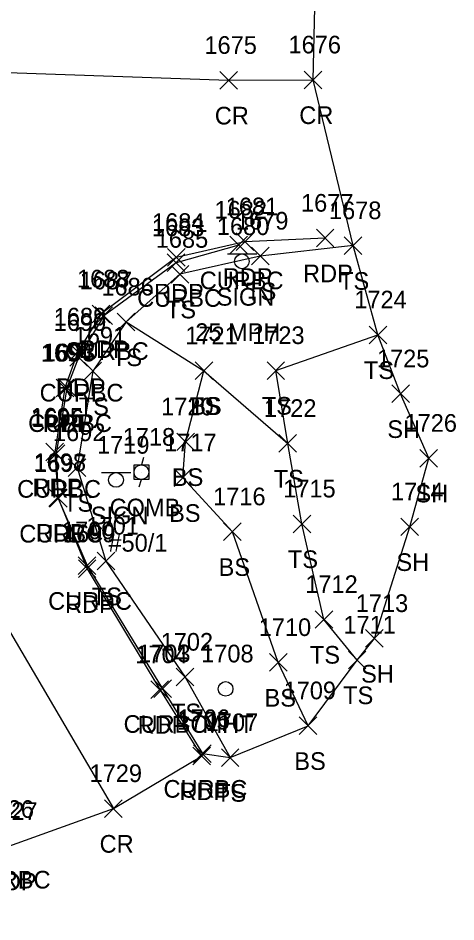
# Model space of a CAD drawing. Extents: x 1716490 to 1717645, y 888034 to 890004.
# Drawn here: x 1717595.6 to 1717645.2, y 888181.8 to 888284.2 of the extents above; entities that cross this region are included whole.
import ezdxf

# ---------------------------------------------------------------- set-up
doc = ezdxf.new("R2010")
doc.units = 0
for name, color, linetype in [('L_A', 7, 'Continuous'), ('L_I', 7, 'Continuous'), ('L_TIC', 7, 'Continuous'), ('LELB', 7, 'Continuous'), ('LSOGP', 7, 'Continuous'), ('P_A', 7, 'Continuous'), ('P_I', 7, 'Continuous'), ('P_TIC', 7, 'Continuous'), ('PET', 7, 'Continuous'), ('PRC', 7, 'Continuous'), ('R_A', 7, 'Continuous'), ('R_I', 7, 'Continuous'), ('R_TIC', 7, 'Continuous'), ('RC', 7, 'Continuous'), ('S_A', 7, 'Continuous'), ('S_C', 7, 'Continuous'), ('S_I', 7, 'Continuous'), ('SSGN', 7, 'Continuous'), ('U_A', 7, 'Continuous'), ('U_C', 7, 'Continuous'), ('U_I', 7, 'Continuous'), ('UP', 7, 'Continuous'), ('UTMH', 7, 'Continuous')]:
    doc.layers.add(name, color=color, linetype=linetype)

msp = doc.modelspace()

# ---------------------------------------------------------------- linework, layer by layer
at = {"layer": 'L_TIC'}
for points in [[(1717632.57, 888257.39), (1717634.57, 888259.39)], [(1717634.57, 888257.39), (1717632.57, 888259.39)], [(1717622.03, 888256.21), (1717624.03, 888258.21)], [(1717624.03, 888256.21), (1717622.03, 888258.21)], [(1717612.92, 888254.15), (1717614.92, 888256.15)], [(1717614.92, 888254.15), (1717612.92, 888256.15)], [(1717606.81, 888248.74), (1717608.81, 888250.74)], [(1717608.81, 888248.74), (1717606.81, 888250.74)], [(1717606.81, 888248.74), (1717608.81, 888250.74)], [(1717608.81, 888248.74), (1717606.81, 888250.74)], [(1717635.39, 888247.28), (1717637.39, 888249.28)], [(1717637.39, 888247.28), (1717635.39, 888249.28)], [(1717603.04, 888243.18), (1717605.04, 888245.18)], [(1717605.04, 888243.18), (1717603.04, 888245.18)], [(1717615.65, 888243.22), (1717617.65, 888245.22)], [(1717617.65, 888243.22), (1717615.65, 888245.22)], [(1717615.65, 888243.22), (1717617.65, 888245.22)], [(1717617.65, 888243.22), (1717615.65, 888245.22)], [(1717623.8, 888243.24), (1717625.8, 888245.24)], [(1717625.8, 888243.24), (1717623.8, 888245.24)], [(1717637.96, 888240.6), (1717639.96, 888242.6)], [(1717639.96, 888240.6), (1717637.96, 888242.6)], [(1717613.57, 888235.16), (1717615.57, 888237.16)], [(1717615.57, 888235.16), (1717613.57, 888237.16)], [(1717625.15, 888234.98), (1717627.15, 888236.98)], [(1717627.15, 888234.98), (1717625.15, 888236.98)], [(1717625.15, 888234.98), (1717627.15, 888236.98)], [(1717627.15, 888234.98), (1717625.15, 888236.98)], [(1717641.15, 888233.3), (1717643.15, 888235.3)], [(1717643.15, 888233.3), (1717641.15, 888235.3)], [(1717601.26, 888232.24), (1717603.26, 888234.24)], [(1717603.26, 888232.24), (1717601.26, 888234.24)], [(1717613.25, 888231.09), (1717615.25, 888233.09)], [(1717615.25, 888231.09), (1717613.25, 888233.09)], [(1717626.76, 888225.86), (1717628.76, 888227.86)], [(1717628.76, 888225.86), (1717626.76, 888227.86)], [(1717639, 888225.53), (1717641, 888227.53)], [(1717641, 888225.53), (1717639, 888227.53)], [(1717618.87, 888224.97), (1717620.87, 888226.97)], [(1717620.87, 888224.97), (1717618.87, 888226.97)], [(1717604.53, 888221.65), (1717606.53, 888223.65)], [(1717606.53, 888221.65), (1717604.53, 888223.65)], [(1717629.26, 888215.03), (1717631.26, 888217.03)], [(1717631.26, 888215.03), (1717629.26, 888217.03)], [(1717634.99, 888212.88), (1717636.99, 888214.88)], [(1717636.99, 888212.88), (1717634.99, 888214.88)], [(1717624.07, 888210.16), (1717626.07, 888212.16)], [(1717626.07, 888210.16), (1717624.07, 888212.16)], [(1717633.03, 888210.44), (1717635.03, 888212.44)], [(1717635.03, 888210.44), (1717633.03, 888212.44)], [(1717613.5, 888208.5), (1717615.5, 888210.5)], [(1717615.5, 888208.5), (1717613.5, 888210.5)], [(1717627.46, 888202.99), (1717629.46, 888204.99)], [(1717629.46, 888202.99), (1717627.46, 888204.99)], [(1717618.62, 888199.38), (1717620.62, 888201.38)], [(1717620.62, 888199.38), (1717618.62, 888201.38)]]:
    msp.add_lwpolyline(points, dxfattribs=at)
at = {"layer": 'LELB'}
for points in [[(1717633.57, 888258.39), (1717623.03, 888257.21), (1717613.92, 888255.15), (1717607.81, 888249.74), (1717604.04, 888244.18), (1717602.26, 888233.24), (1717605.53, 888222.65), (1717614.5, 888209.5), (1717619.62, 888200.38)], [(1717607.81, 888249.74), (1717616.65, 888244.22), (1717626.15, 888235.98)], [(1717634.03, 888211.44), (1717630.26, 888216.03), (1717627.76, 888226.86), (1717626.15, 888235.98), (1717624.8, 888244.24), (1717636.39, 888248.28)], [(1717628.46, 888203.99), (1717625.07, 888211.16), (1717619.87, 888225.97), (1717614.25, 888232.09), (1717614.57, 888236.16), (1717616.65, 888244.22)]]:
    msp.add_lwpolyline(points, dxfattribs=at)
at = {"layer": 'LSOGP'}
msp.add_lwpolyline([(1717512.34, 888207.14), (1717547.36, 888203.24), (1717562.88, 888195.85), (1717574.35, 888181.76), (1717589.34, 888189.72), (1717590.1, 888189.33), (1717594.16, 888190.55), (1717594.52, 888190.33), (1717606.37, 888194.61), (1717616.38, 888200.56), (1717616.48, 888200.84), (1717619.62, 888200.38), (1717628.46, 888203.99), (1717634.03, 888211.44), (1717635.99, 888213.88), (1717640, 888226.53), (1717642.15, 888234.3), (1717638.96, 888241.6), (1717636.39, 888248.28), (1717633.57, 888258.39), (1717629.03, 888277.17), (1717629.47, 888295.32)], dxfattribs=at)
at = {"layer": 'P_TIC'}
for points in [[(1717618.44, 888276.12), (1717620.44, 888278.12)], [(1717620.44, 888276.12), (1717618.44, 888278.12)], [(1717628.03, 888276.17), (1717630.03, 888278.17)], [(1717630.03, 888276.17), (1717628.03, 888278.17)], [(1717629.4, 888258.24), (1717631.4, 888260.24)], [(1717631.4, 888258.24), (1717629.4, 888260.24)], [(1717620.29, 888257.83), (1717622.29, 888259.83)], [(1717622.29, 888257.83), (1717620.29, 888259.83)], [(1717612.5, 888256.06), (1717614.5, 888258.06)], [(1717614.5, 888256.06), (1717612.5, 888258.06)], [(1717603.98, 888249.65), (1717605.98, 888251.65)], [(1717605.98, 888249.65), (1717603.98, 888251.65)], [(1717601.35, 888245.34), (1717603.35, 888247.34)], [(1717603.35, 888245.34), (1717601.35, 888247.34)], [(1717599.88, 888241.26), (1717601.88, 888243.26)], [(1717601.88, 888241.26), (1717599.88, 888243.26)], [(1717598.72, 888234), (1717600.72, 888236)], [(1717600.72, 888234), (1717598.72, 888236)], [(1717599.06, 888228.84), (1717601.06, 888230.84)], [(1717601.06, 888228.84), (1717599.06, 888230.84)], [(1717602.4, 888220.78), (1717604.4, 888222.78)], [(1717604.4, 888220.78), (1717602.4, 888222.78)], [(1717610.63, 888207.08), (1717612.63, 888209.08)], [(1717612.63, 888207.08), (1717610.63, 888209.08)], [(1717615.38, 888199.56), (1717617.38, 888201.56)], [(1717617.38, 888199.56), (1717615.38, 888201.56)], [(1717605.37, 888193.61), (1717607.37, 888195.61)], [(1717607.37, 888193.61), (1717605.37, 888195.61)]]:
    msp.add_lwpolyline(points, dxfattribs=at)
at = {"layer": 'PET'}
msp.add_lwpolyline([(1717630.4, 888259.24), (1717621.29, 888258.83), (1717613.5, 888257.06), (1717604.98, 888250.65), (1717602.35, 888246.34), (1717600.88, 888242.26), (1717599.72, 888235), (1717600.06, 888229.84), (1717603.4, 888221.78), (1717611.63, 888208.08), (1717616.38, 888200.56)], dxfattribs=at)
at = {"layer": 'PRC'}
for points in [[(1717436.1, 888262.99), (1717458.49, 888266.27), (1717492.01, 888269.4), (1717536.7, 888274.82), (1717555.46, 888275.73), (1717587.78, 888278.25), (1717619.44, 888277.12), (1717629.03, 888277.17)], [(1717555.46, 888275.73), (1717576.67, 888244.75), (1717588.48, 888225.03), (1717606.37, 888194.61)]]:
    msp.add_lwpolyline(points, dxfattribs=at)
at = {"layer": 'R_TIC'}
for points in [[(1717619.59, 888257.45), (1717621.59, 888259.45)], [(1717621.59, 888257.45), (1717619.59, 888259.45)], [(1717612.48, 888255.46), (1717614.48, 888257.46)], [(1717614.48, 888255.46), (1717612.48, 888257.46)], [(1717604.29, 888249.44), (1717606.29, 888251.44)], [(1717606.29, 888249.44), (1717604.29, 888251.44)], [(1717601.42, 888244.73), (1717603.42, 888246.73)], [(1717603.42, 888244.73), (1717601.42, 888246.73)], [(1717600.11, 888241.28), (1717602.11, 888243.28)], [(1717602.11, 888241.28), (1717600.11, 888243.28)], [(1717598.88, 888233.83), (1717600.88, 888235.83)], [(1717600.88, 888233.83), (1717598.88, 888235.83)], [(1717599.12, 888228.75), (1717601.12, 888230.75)], [(1717601.12, 888228.75), (1717599.12, 888230.75)], [(1717602.39, 888221.13), (1717604.39, 888223.13)], [(1717604.39, 888221.13), (1717602.39, 888223.13)], [(1717610.95, 888207.19), (1717612.95, 888209.19)], [(1717612.95, 888207.19), (1717610.95, 888209.19)], [(1717615.48, 888199.84), (1717617.48, 888201.84)], [(1717617.48, 888199.84), (1717615.48, 888201.84)]]:
    msp.add_lwpolyline(points, dxfattribs=at)
at = {"layer": 'RC'}
msp.add_lwpolyline([(1717620.59, 888258.45), (1717613.48, 888256.46), (1717605.29, 888250.44), (1717602.42, 888245.73), (1717601.11, 888242.28), (1717599.88, 888234.83), (1717600.12, 888229.75), (1717603.39, 888222.13), (1717611.95, 888208.19), (1717616.48, 888200.84)], dxfattribs=at)
at = {"layer": 'SSGN'}
for p, q in [((1717619.31, 888257.45), (1717622.64, 888257.45)), ((1717620.95, 888256.61), (1717620.95, 888256.61)), ((1717605.03, 888232.67), (1717608.36, 888232.67)), ((1717606.67, 888231.84), (1717606.67, 888231.84))]:
    msp.add_line(p, q, dxfattribs=at)
for centre in [(1717620.95, 888256.61), (1717606.67, 888231.84)]:
    msp.add_circle(centre, 0.833, dxfattribs=at)
at = {"layer": 'UP'}
for p, q in [((1717609.8, 888234.38), (1717609.55, 888233.55)), ((1717608.72, 888231.88), (1717608.72, 888233.55)), ((1717608.72, 888233.55), (1717610.39, 888233.55)), ((1717609.55, 888232.72), (1717609.55, 888232.72)), ((1717610.39, 888233.55), (1717610.39, 888231.88)), ((1717610.39, 888231.88), (1717608.72, 888231.88)), ((1717609.3, 888231.05), (1717609.55, 888231.88))]:
    msp.add_line(p, q, dxfattribs=at)
msp.add_circle((1717609.55, 888232.72), 0.833, dxfattribs=at)
at = {"layer": 'UTMH'}
for p, q in [((1717619.1, 888208.17), (1717619.1, 888208.17)), ((1717619.93, 888208.17), (1717619.93, 888208.17))]:
    msp.add_line(p, q, dxfattribs=at)
msp.add_circle((1717619.1, 888208.17), 0.833, dxfattribs=at)

# ---------------------------------------------------------------- texts
at = {"layer": 'L_A'}
for s, p in [('TS', (1717631.98, 888253.39)), ('TS', (1717621.44, 888252.21)), ('TS', (1717612.33, 888250.15)), ('TS', (1717606.22, 888244.74)), ('TS', (1717606.22, 888244.74)), ('TS', (1717634.8, 888243.28)), ('TS', (1717602.45, 888239.18)), ('TS', (1717615.06, 888239.22)), ('BS', (1717615.09, 888239.22)), ('TS', (1717623.21, 888239.24)), ('SH', (1717637.45, 888236.6)), ('BS', (1717613.01, 888231.16)), ('TS', (1717624.56, 888230.98)), ('TS', (1717624.56, 888230.98)), ('SH', (1717640.64, 888229.3)), ('TS', (1717600.67, 888228.24)), ('BS', (1717612.69, 888227.09)), ('TS', (1717626.17, 888221.86)), ('SH', (1717638.49, 888221.53)), ('BS', (1717618.31, 888220.97)), ('TS', (1717603.93, 888217.65)), ('TS', (1717628.67, 888211.03)), ('SH', (1717634.48, 888208.88)), ('BS', (1717623.52, 888206.16)), ('TS', (1717632.44, 888206.44)), ('TS', (1717612.91, 888204.5)), ('BS', (1717626.9, 888198.99)), ('TS', (1717618.03, 888195.38))]:
    msp.add_text(s, height=2, dxfattribs=at).set_placement(p)
at = {"layer": 'L_I'}
for s, p in [('1678', (1717630.83, 888261.39)), ('1679', (1717620.28, 888260.21)), ('1685', (1717611.18, 888258.15)), ('1686', (1717605.01, 888252.74)), ('1686', (1717605.01, 888252.74)), ('1724', (1717633.7, 888251.28)), ('1691', (1717601.87, 888247.18)), ('1721', (1717614.53, 888247.22)), ('1721', (1717614.53, 888247.22)), ('1723', (1717622.11, 888247.24)), ('1725', (1717636.27, 888244.6)), ('1720', (1717611.79, 888239.16)), ('1722', (1717623.46, 888238.98)), ('1722', (1717623.46, 888238.98)), ('1726', (1717639.4, 888237.3)), ('1692', (1717599.52, 888236.24)), ('1717', (1717612.13, 888235.09)), ('1715', (1717625.64, 888229.86)), ('1716', (1717617.69, 888228.97)), ('1714', (1717637.87, 888229.53)), ('1701', (1717603.32, 888225.65)), ('1712', (1717628.14, 888219.03)), ('1713', (1717633.87, 888216.88)), ('1710', (1717622.86, 888214.16)), ('1711', (1717632.47, 888214.44)), ('1702', (1717611.73, 888212.5)), ('1709', (1717625.68, 888206.99)), ('1707', (1717616.85, 888203.38))]:
    msp.add_text(s, height=2, dxfattribs=at).set_placement(p)
at = {"layer": 'P_A'}
for s, p in [('CR', (1717617.88, 888272.12)), ('CR', (1717627.46, 888272.17)), ('RDP', (1717627.89, 888254.24)), ('RDP', (1717618.78, 888253.83)), ('RDP', (1717610.98, 888252.06)), ('RDP', (1717602.47, 888245.65)), ('RDP', (1717599.84, 888241.34)), ('RDP', (1717598.37, 888237.26)), ('RDP', (1717597.2, 888230)), ('RDP', (1717597.55, 888224.84)), ('RDP', (1717600.88, 888216.78)), ('RDP', (1717609.12, 888203.08)), ('RDP', (1717613.87, 888195.56)), ('CR', (1717604.81, 888189.61)), ('RDP', (1717592.01, 888185.33))]:
    msp.add_text(s, height=2, dxfattribs=at).set_placement(p)
at = {"layer": 'P_I'}
for s, p in [('1675', (1717616.7, 888280.12)), ('1676', (1717626.24, 888280.17)), ('1681', (1717619.12, 888261.83)), ('1677', (1717627.66, 888262.24)), ('1684', (1717610.76, 888260.06)), ('1688', (1717602.24, 888253.65)), ('1689', (1717599.61, 888249.34)), ('1694', (1717598.14, 888245.26)), ('1695', (1717596.98, 888238)), ('1698', (1717597.32, 888232.84)), ('1699', (1717600.65, 888224.78)), ('1704', (1717608.86, 888211.08)), ('1705', (1717613.61, 888203.56)), ('1729', (1717603.67, 888197.61)), ('1427', (1717591.82, 888193.33))]:
    msp.add_text(s, height=2, dxfattribs=at).set_placement(p)
at = {"layer": 'R_A'}
for p in [(1717616.17, 888253.45), (1717609.07, 888251.46), (1717600.87, 888245.44), (1717598.01, 888240.73), (1717596.7, 888237.28), (1717595.46, 888229.83), (1717595.7, 888224.75), (1717598.97, 888217.13), (1717607.53, 888203.19), (1717612.06, 888195.84), (1717589.74, 888185.55)]:
    msp.add_text('CURBC', height=2, dxfattribs=at).set_placement(p)
at = {"layer": 'R_I'}
for s, p in [('1682', (1717617.85, 888261.45)), ('1683', (1717610.74, 888259.46)), ('1687', (1717602.55, 888253.44)), ('1690', (1717599.6, 888248.73)), ('1693', (1717598.37, 888245.28)), ('1696', (1717597.08, 888237.83)), ('1697', (1717597.38, 888232.75)), ('1700', (1717600.53, 888225.13)), ('1703', (1717609.17, 888211.19)), ('1706', (1717613.65, 888203.84)), ('1426', (1717591.41, 888193.55))]:
    msp.add_text(s, height=2, dxfattribs=at).set_placement(p)
at = {"layer": 'S_A'}
for p in [(1717618.09, 888251.59), (1717603.81, 888226.82)]:
    msp.add_text('SIGN', height=2, dxfattribs=at).set_placement(p)
at = {"layer": 'S_C'}
msp.add_text('25 MPH', height=2, dxfattribs=at).set_placement((1717615.66, 888247.59))
at = {"layer": 'S_I'}
for s, p in [('1680', (1717618.11, 888259.59)), ('1719', (1717604.52, 888234.82))]:
    msp.add_text(s, height=2, dxfattribs=at).set_placement(p)
at = {"layer": 'U_A'}
for s, p in [('COMB', (1717605.94, 888227.72)), ('MHT', (1717616.48, 888203.17))]:
    msp.add_text(s, height=2, dxfattribs=at).set_placement(p)
at = {"layer": 'U_C'}
msp.add_text('#50/1', height=2, dxfattribs=at).set_placement((1717605.81, 888223.72))
at = {"layer": 'U_I'}
for s, p in [('1718', (1717607.43, 888235.72)), ('1708', (1717616.33, 888211.17))]:
    msp.add_text(s, height=2, dxfattribs=at).set_placement(p)

doc.saveas('drawing.dxf')
